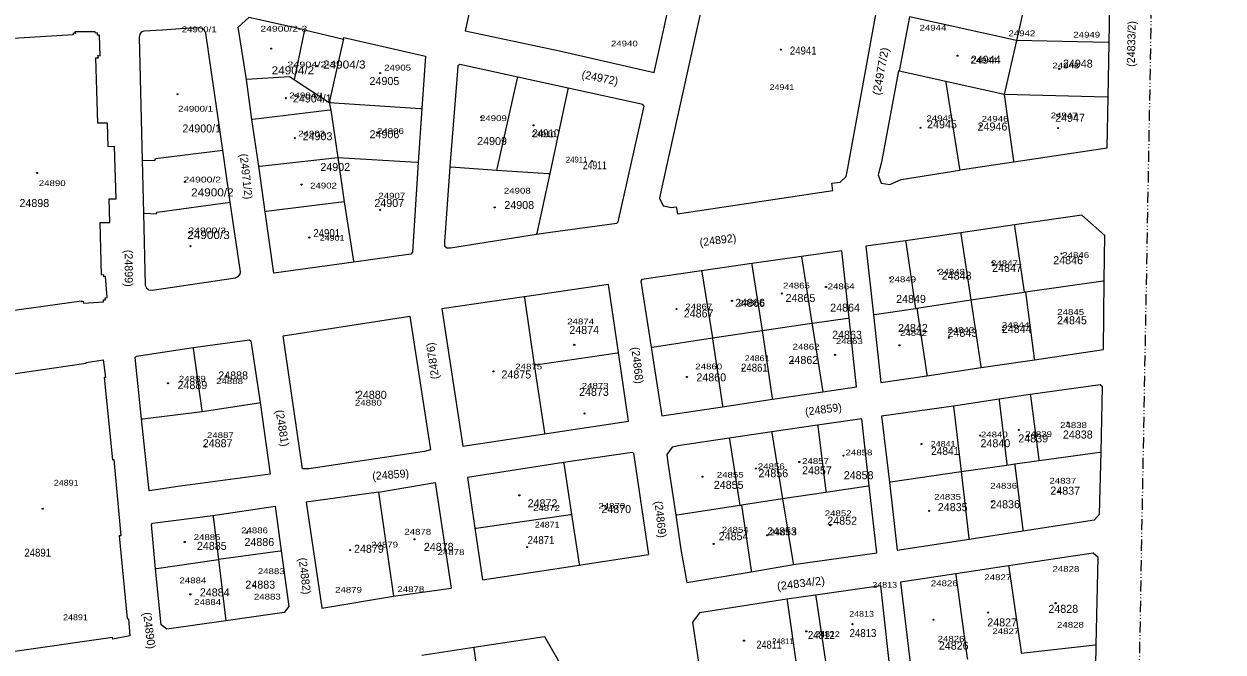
# Model space of a CAD drawing. Extents: x 649608 to 651081, y 237980 to 241202.
# Drawn here: x 650066 to 650605, y 240222 to 240505 of the extents above; entities that cross this region are included whole.
import ezdxf

# ---------------------------------------------------------------- set-up
doc = ezdxf.new("R2010")
doc.units = 0
doc.header["$PDMODE"] = 32
doc.header["$PDSIZE"] = 0.5
doc.linetypes.add('DASH_DOUBLE_DOT', pattern=[9.2, 5, -1.2, 0.3, -1.2, 0.3, -1.2])
for name, color, linetype in [('19', 7, 'Continuous'), ('20', 7, 'Continuous'), ('6', 7, 'Continuous')]:
    doc.layers.add(name, color=color, linetype=linetype)
for name, color, linetype, lineweight in [('3', 7, 'Continuous', 13), ('5', 7, 'Continuous', 13), ('52', 7, 'DASH_DOUBLE_DOT', 13)]:
    doc.layers.add(name, color=color, linetype=linetype, lineweight=lineweight)

msp = doc.modelspace()

# ---------------------------------------------------------------- linework, layer by layer
at = {"layer": '3'}
for p, q in [((650464.38, 240507.741), (650459.782, 240483.398)), ((650192.146, 240501.902), (650209.762, 240497.751)), ((650100.313, 240490.228), (650100.028, 240499.595)), ((650393.376, 240396.857), (650370.795, 240393.616)), ((650451.842, 240328.356), (650455.303, 240298.708)), ((650122.263, 240294.737), (650118.945, 240327.041)), ((650442.889, 240327.116), (650422.995, 240324.266)), ((650340.221, 240311.728), (650346.915, 240266.06)), ((650225.498, 240294.168), (650250.969, 240298.542)), ((650250.969, 240298.542), (650258.175, 240251.056)), ((650451.519, 240252.086), (650422.153, 240247.787)), ((650156.768, 240236.355), (650130.262, 240232.545))]:
    msp.add_line(p, q, dxfattribs=at)
for points in [[(650367.209, 240562.582), (650368.783, 240569.636), (650368.608, 240571.167), (650367.259, 240572.096), (650286.579, 240591.249), (650284.955, 240591.124), (650284.131, 240589.969), (650282.457, 240582.689), (650264.467, 240501.506)], [(650382.8, 240566.096), (650352.577, 240429.937), (650351.943, 240426.301), (650353.603, 240422.893), (650357.329, 240422.137), (650359.471, 240422.441), (650359.933, 240419.311), (650429.951, 240429.763), (650429.439, 240432.969), (650433.112, 240433.476), (650435.814, 240436.102), (650436.576, 240439.789), (650456.358, 240548.398)], [(650264.467, 240501.506), (650306.865, 240492.557), (650349.449, 240482.852), (650367.209, 240562.582)], [(650511.154, 240442.644), (650511.32, 240442.669), (650553.356, 240448.971), (650553.746, 240471.66), (650554.168, 240496.192), (650554.749, 240529.941)], [(650192.146, 240501.902), (650167.155, 240507.496), (650162.349, 240503.208)], [(650100.028, 240499.595), (650099.147, 240499.556), (650099.059, 240500.551), (650098.128, 240500.488), (650098.035, 240501.11), (650088.929, 240501.003), (650089.121, 240500.255), (650088.092, 240500.442), (650088.158, 240499.721), (650056.369, 240497.741)], [(650155.442, 240447.926), (650147.749, 240500.428), (650147.186, 240501.652), (650146.142, 240502.609), (650144.811, 240502.825), (650136.255, 240502.412), (650128.376, 240501.842), (650119.868, 240501.329), (650118.68, 240500.848), (650118.066, 240500.036), (650117.773, 240498.698), (650119.117, 240443.322), (650119.701, 240419.596)], [(650214.393, 240397.528), (650178.466, 240392.571), (650174.486, 240420.19), (650171.673, 240440.616), (650168.466, 240461.644), (650166.15, 240479.629), (650162.349, 240503.208)], [(650209.762, 240497.751), (650209.923, 240498.519), (650246.613, 240490.129), (650244.934, 240466.532), (650243.299, 240442.387)], [(650059.467, 240375.583), (650091.818, 240380.163), (650091.888, 240379.74), (650092.62, 240379.93), (650092.786, 240379.133), (650101.847, 240379.688), (650101.833, 240380.533), (650102.713, 240380.571), (650102.55, 240381.567), (650103.481, 240381.629), (650102.668, 240391.028), (650101.863, 240390.963), (650101.95, 240391.906), (650100.841, 240391.746), (650100.257, 240415.422), (650104.633, 240415.416), (650104.363, 240425.975), (650107.406, 240425.961), (650106.77, 240449.489), (650103.826, 240449.378), (650103.582, 240460.06), (650099.28, 240459.966), (650098.341, 240489.384), (650099.497, 240489.344), (650099.259, 240490.366), (650100.313, 240490.228)], [(650288.198, 240480.741), (650264.242, 240486.002), (650262.124, 240486.33), (650261.206, 240485.723), (650260.978, 240483.527), (650257.542, 240440.48), (650257.534, 240440.368)], [(650345.022, 240467.678), (650344.461, 240468.384), (650310.826, 240475.771), (650288.198, 240480.741)], [(650459.782, 240483.398), (650459.399, 240483.524), (650451.804, 240442.496), (650450.303, 240436.815), (650451.658, 240433.003), (650455.562, 240432.373), (650460.586, 240434.647), (650486.947, 240438.939)], [(650296.639, 240410.084), (650302.872, 240411.06), (650332.767, 240415.085), (650333.328, 240415.64), (650345.022, 240467.678)], [(650119.701, 240419.596), (650120.578, 240387.198), (650121.116, 240385.975), (650122.161, 240385.092), (650123.668, 240384.899), (650161.212, 240390.506), (650162.426, 240391.062), (650163.219, 240392.07), (650163.434, 240393.21), (650158.796, 240424.512), (650155.442, 240447.926)], [(650243.299, 240442.387), (650240.732, 240402.036), (650239.965, 240401.102), (650214.393, 240397.528)], [(650486.947, 240438.939), (650487.164, 240438.974), (650511.154, 240442.644)], [(650257.534, 240440.368), (650255.171, 240406.624), (650255.121, 240404.932), (650256.244, 240403.923), (650257.851, 240403.974), (650263.54, 240404.885), (650296.572, 240410.073), (650296.639, 240410.084)], [(650552.188, 240409.485), (650541.824, 240418.721), (650511.57, 240414.271), (650487.428, 240410.72), (650462.591, 240407.067)], [(650448.146, 240373.862), (650451.448, 240343.428), (650472.187, 240346.506), (650496.604, 240350.129), (650520.565, 240353.685), (650551.565, 240358.285), (650551.942, 240389.236), (650552.188, 240409.485)], [(650462.591, 240407.067), (650462.495, 240407.053), (650444.792, 240404.775), (650448.146, 240373.862)], [(650348.1, 240359.263), (650352.886, 240328.421), (650380.267, 240332.524), (650402.707, 240335.887), (650425.332, 240339.278), (650440.531, 240341.556), (650437.178, 240372.47), (650433.901, 240402.675)], [(650433.901, 240402.675), (650415.741, 240400.068), (650393.376, 240396.857)], [(650370.795, 240393.616), (650343.986, 240389.767), (650343.477, 240389.059), (650348.1, 240359.263)], [(650328.911, 240387.438), (650291.134, 240382.022), (650291.034, 240382.007)], [(650300.175, 240320.388), (650338.016, 240326.067), (650333.443, 240356.891), (650328.911, 240387.438)], [(650291.034, 240382.007), (650254.046, 240376.479), (650263.482, 240314.881), (650300.175, 240320.388)], [(650142.108, 240359.182), (650167.453, 240362.66), (650168.076, 240362.23), (650172.23, 240334.385)], [(650118.945, 240327.041), (650116.072, 240354.72), (650116.633, 240355.334), (650142.108, 240359.182)], [(650059.084, 240347.002), (650093.981, 240352.071), (650093.986, 240352.468), (650101.672, 240353.637), (650102.729, 240345.676), (650102.075, 240345.684), (650105.862, 240308.606), (650106.468, 240308.772), (650109.636, 240274.582), (650108.831, 240274.518), (650112.415, 240237.392), (650113.017, 240237.26), (650113.65, 240229.528), (650105.986, 240228.11), (650105.869, 240228.782), (650061.877, 240222.463)], [(650550.54, 240312.255), (650551.221, 240341.496), (650550.174, 240342.429), (650518.774, 240338), (650518.691, 240337.988), (650504.653, 240335.908), (650484.158, 240332.873), (650484.084, 240332.862), (650451.842, 240328.356)], [(650172.23, 240334.385), (650176.782, 240302.214), (650136.222, 240296.82), (650122.263, 240294.737)], [(650422.995, 240324.266), (650402.434, 240321.32), (650402.362, 240321.309), (650383.261, 240318.451)], [(650412.155, 240261.578), (650412.225, 240261.59), (650449.645, 240266.905), (650446.273, 240296.959), (650442.889, 240327.116)], [(650383.261, 240318.451), (650361.162, 240315.144), (650357.591, 240314.31), (650355.17, 240311.002), (650355.607, 240307.291), (650359.202, 240283.753)], [(650340.221, 240311.728), (650339.608, 240311.93), (650308.744, 240307.475), (650308.736, 240307.474)], [(650515.39, 240276.743), (650547.594, 240281.685), (650549.888, 240284.211), (650550.54, 240312.255)], [(650308.736, 240307.474), (650265.483, 240300.794), (650268.862, 240277.919)], [(650455.303, 240298.708), (650458.879, 240268.07), (650491.19, 240273.029), (650515.39, 240276.743)], [(650225.498, 240294.168), (650193.022, 240289.614), (650199.999, 240242.163), (650199.997, 240242.039), (650232.257, 240247.39), (650258.175, 240251.056)], [(650150.997, 240283.692), (650178.942, 240287.906), (650181.707, 240267.729)], [(650125.145, 240259.756), (650123.355, 240279.573), (650123.841, 240280.188), (650150.997, 240283.692)], [(650359.202, 240283.753), (650361.556, 240268.337), (650364.195, 240253.519), (650393.211, 240258.395), (650412.155, 240261.578)], [(650268.862, 240277.919), (650272.28, 240254.773), (650315.825, 240261.354)], [(650181.707, 240267.729), (650185.142, 240242.725), (650183.097, 240240.118), (650156.768, 240236.355)], [(650315.825, 240261.354), (650316.484, 240261.454), (650346.915, 240266.06)], [(650548.41, 240225.505), (650549.266, 240264.771), (650546.994, 240266.689), (650508.951, 240260.965), (650485.214, 240257.393), (650460.37, 240253.655)], [(650130.262, 240232.545), (650127.746, 240234.489), (650125.145, 240259.756)], [(650460.37, 240253.655), (650464.813, 240216.218), (650467.034, 240197.497), (650471.435, 240160.411)], [(650422.153, 240247.787), (650422.134, 240247.784), (650409.227, 240245.987), (650409.196, 240245.982)], [(650459.759, 240178.093), (650456.889, 240203.161), (650456.873, 240203.307), (650454.806, 240222.136), (650451.519, 240252.086)], [(650409.196, 240245.982), (650369.92, 240239.938), (650366.735, 240235.721), (650370.821, 240208.803), (650375.407, 240178.587), (650380.061, 240147.931), (650384.882, 240116.168), (650389.996, 240082.478)], [(650245.029, 240220.902), (650268.31, 240224.434), (650300.106, 240229.259)], [(650300.106, 240229.259), (650309.685, 240212.852), (650289.846, 240187.623), (650266.349, 240157.741), (650250.168, 240137.164)], [(650547.448, 240170.665), (650547.985, 240206.022), (650547.986, 240206.073), (650548.41, 240225.505)]]:
    msp.add_lwpolyline(points, dxfattribs=at)
msp.add_lwpolyline([(650182.541, 240364.455), (650239.541, 240373.241), (650248.9, 240313.168), (650246.225, 240312.432), (650194.192, 240304.7), (650191.374, 240304.636)], close=True, dxfattribs=at)
at = {"layer": '5'}
for p, q in [((650415.741, 240400.068), (650420.451, 240370.075)), ((650491.987, 240380.618), (650515.92, 240384.058)), ((650515.92, 240384.058), (650516.52, 240384.145)), ((650484.158, 240332.873), (650487.625, 240303.366)), ((650225.498, 240294.168), (650232.257, 240247.39)), ((650387.969, 240288.191), (650388.786, 240288.267))]:
    msp.add_line(p, q, dxfattribs=at)
for points in [[(650521.636, 240537.673), (650521.522, 240537.173), (650512.428, 240497.215), (650506.903, 240472.938)], [(650554.168, 240496.192), (650553.668, 240496.204), (650512.428, 240497.215), (650464.38, 240507.741)], [(650192.146, 240501.902), (650187.578, 240479.555), (650185.407, 240480.899), (650166.15, 240479.629)], [(650209.762, 240497.751), (650209.649, 240497.251), (650203.371, 240469.37), (650204.032, 240465.91), (650207.235, 240444.56), (650209.979, 240424.631)], [(650187.578, 240479.555), (650188.078, 240479.233), (650203.371, 240469.37)], [(650278.768, 240438.94), (650278.881, 240439.44), (650288.085, 240480.241), (650288.198, 240480.741)], [(650553.746, 240471.66), (650553.246, 240471.674), (650506.903, 240472.938), (650480.702, 240478.754), (650459.782, 240483.398)], [(650310.826, 240475.771), (650310.718, 240475.271), (650302.526, 240437.343)], [(650480.702, 240478.754), (650480.78, 240478.254), (650486.869, 240439.439), (650486.947, 240438.939)], [(650203.371, 240469.37), (650244.434, 240466.566), (650244.934, 240466.532)], [(650506.903, 240472.938), (650511.084, 240443.144), (650511.154, 240442.644)], [(650204.032, 240465.91), (650203.532, 240465.85), (650168.966, 240461.704), (650168.466, 240461.644)], [(650119.117, 240443.322), (650119.617, 240443.311), (650124.8, 240443.2), (650125.189, 240444.188), (650155.442, 240447.926)], [(650171.673, 240440.616), (650172.173, 240440.671), (650207.235, 240444.56)], [(650207.235, 240444.56), (650242.799, 240442.417), (650243.299, 240442.387)], [(650257.534, 240440.368), (650258.034, 240440.334), (650278.768, 240438.94)], [(650278.768, 240438.94), (650302.026, 240437.377), (650302.526, 240437.343)], [(650302.526, 240437.343), (650296.747, 240410.583), (650296.639, 240410.084)], [(650119.701, 240419.596), (650120.201, 240419.568), (650125.456, 240419.274), (650125.969, 240420.062), (650158.796, 240424.512)], [(650209.979, 240424.631), (650174.986, 240420.253), (650174.486, 240420.19)], [(650209.979, 240424.631), (650214.312, 240398.028), (650214.393, 240397.528)], [(650511.57, 240414.271), (650511.642, 240413.771), (650515.92, 240384.058)], [(650487.428, 240410.72), (650487.504, 240410.22), (650491.987, 240380.618)], [(650462.591, 240407.067), (650462.664, 240406.567), (650467.014, 240376.77)], [(650370.795, 240393.616), (650370.877, 240393.116), (650375.731, 240363.448)], [(650393.376, 240396.857), (650393.455, 240396.357), (650398.133, 240366.867)], [(650516.52, 240384.145), (650551.442, 240389.164), (650551.942, 240389.236)], [(650291.034, 240382.007), (650291.108, 240381.507), (650295.58, 240351.364)], [(650516.52, 240384.145), (650520.499, 240354.185), (650520.565, 240353.685)], [(650448.146, 240373.862), (650448.646, 240373.939), (650467.014, 240376.77), (650467.64, 240376.867)], [(650467.64, 240376.867), (650491.904, 240380.606), (650491.987, 240380.618)], [(650467.64, 240376.867), (650472.112, 240347.006), (650472.187, 240346.506)], [(650491.987, 240380.618), (650496.528, 240350.629), (650496.604, 240350.129)], [(650420.451, 240370.075), (650420.557, 240370.09), (650436.678, 240372.398), (650437.178, 240372.47)], [(650348.1, 240359.263), (650348.6, 240359.339), (650375.731, 240363.448), (650398.133, 240366.867), (650420.451, 240370.075)], [(650398.133, 240366.867), (650398.138, 240366.837), (650402.633, 240336.387), (650402.707, 240335.887)], [(650420.451, 240370.075), (650420.559, 240369.386), (650425.332, 240339.278)], [(650375.731, 240363.448), (650375.793, 240363.067), (650380.194, 240333.024), (650380.267, 240332.524)], [(650142.108, 240359.182), (650142.178, 240358.682), (650146.079, 240330.921), (650146.149, 240330.421)], [(650295.58, 240351.364), (650296.08, 240351.437), (650332.943, 240356.818), (650333.443, 240356.891)], [(650295.58, 240351.364), (650300.101, 240320.888), (650300.175, 240320.388)], [(650146.149, 240330.421), (650171.73, 240334.309), (650172.23, 240334.385)], [(650504.653, 240335.908), (650504.713, 240335.408), (650508.163, 240306.834), (650508.223, 240306.334)], [(650518.691, 240337.988), (650518.757, 240337.488), (650522.565, 240308.86), (650522.631, 240308.36)], [(650118.945, 240327.041), (650119.445, 240327.103), (650146.149, 240330.421)], [(650422.995, 240324.266), (650423.057, 240323.766), (650426.668, 240294.564), (650426.73, 240294.064)], [(650383.261, 240318.451), (650383.339, 240317.951), (650387.969, 240288.191)], [(650402.362, 240321.309), (650402.444, 240320.809), (650407.301, 240291.185)], [(650522.631, 240308.36), (650550.041, 240312.185), (650550.54, 240312.255)], [(650308.736, 240307.474), (650308.813, 240306.974), (650312.323, 240284.136)], [(650455.303, 240298.708), (650455.803, 240298.78), (650487.625, 240303.366), (650508.223, 240306.334), (650511.743, 240306.841)], [(650511.743, 240306.841), (650511.758, 240306.843), (650522.631, 240308.36)], [(650511.743, 240306.841), (650511.804, 240306.341), (650515.329, 240277.243), (650515.39, 240276.743)], [(650487.625, 240303.366), (650491.131, 240273.529), (650491.19, 240273.029)], [(650446.273, 240296.959), (650445.773, 240296.885), (650426.73, 240294.064), (650407.301, 240291.185), (650388.786, 240288.267)], [(650407.301, 240291.185), (650412.073, 240262.078), (650412.155, 240261.578)], [(650387.969, 240288.191), (650359.702, 240283.83), (650359.202, 240283.753)], [(650388.786, 240288.267), (650393.137, 240258.895), (650393.211, 240258.395)], [(650150.997, 240283.692), (650151.06, 240283.192), (650153.491, 240263.94), (650156.768, 240236.355)], [(650268.862, 240277.919), (650269.362, 240277.991), (650311.823, 240284.064), (650312.323, 240284.136)], [(650312.323, 240284.136), (650315.748, 240261.854), (650315.825, 240261.354)], [(650125.145, 240259.756), (650125.645, 240259.83), (650153.491, 240263.94)], [(650181.707, 240267.729), (650181.207, 240267.662), (650153.491, 240263.94)], [(650508.951, 240260.965), (650509.023, 240260.465), (650514.54, 240222.272), (650514.612, 240221.772)], [(650485.214, 240257.393), (650485.282, 240256.893), (650490.357, 240219.574), (650490.425, 240219.074)], [(650422.153, 240247.787), (650422.228, 240247.287), (650426.646, 240218.032), (650426.721, 240217.532)], [(650409.196, 240245.982), (650409.268, 240245.482), (650413.524, 240215.891), (650413.596, 240215.391)], [(650514.612, 240221.772), (650547.91, 240225.45), (650548.41, 240225.505)], [(650268.31, 240224.434), (650268.38, 240223.934), (650271.472, 240201.911)]]:
    msp.add_lwpolyline(points, dxfattribs=at)
at = {"layer": '52'}
msp.add_lwpolyline([(650605.404, 240765.589), (650575.102, 240622.376), (650564.111, 240019.547), (650563.292, 239912.239), (650561.967, 239831.306), (650558.948, 239635.138), (650557.76, 239590.469), (650555.824, 239499.761), (650555.114, 239481.758), (650553.994, 239393.396), (650554.019, 239393.395), (650553.222, 239318.763), (650553.006, 239301.006), (650586.911, 239277.281)], dxfattribs=at)
at = {"layer": '6'}
for p in [(650177.172, 240493.525), (650406.438, 240493.08), (650485.978, 240490.339), (650197.927, 240485.636), (650531.743, 240484.437), (650226.203, 240482.525), (650135.081, 240473.012), (650183.825, 240471.271), (650271.712, 240462.635), (650295.258, 240459.042), (650469.315, 240457.948), (650496.353, 240458.846), (650531.268, 240457.791), (650187.837, 240453.263), (650224.875, 240455.878), (650321.596, 240442.927), (650071.901, 240437.617), (650138.425, 240433.6), (650190.86, 240432.375), (650226.252, 240421.044), (650277.751, 240422.145), (650194.373, 240408.601), (650140.917, 240404.705), (650532.757, 240401.389), (650477.267, 240393.745), (650501.716, 240397.444), (650455.68, 240390.464), (650406.924, 240383.467), (650426.78, 240386.375), (650359.52, 240376.439), (650384.512, 240380.152), (650534.965, 240371.46), (650506.404, 240367.137), (650313.584, 240360.382), (650459.889, 240360.147), (650482.101, 240363.562), (650430.84, 240355.874), (650389.21, 240349.695), (650411.672, 240352.981), (650157.15, 240346.54), (650277.177, 240348.444), (650364.236, 240345.934), (650130.822, 240343.111), (650215.597, 240338.938), (650318.163, 240329.513), (650535.606, 240325.394), (650496.165, 240319.637), (650513.554, 240322.161), (650147.631, 240314.561), (650469.737, 240315.79), (650414.815, 240307.725), (650434.715, 240310.59), (650371.256, 240301.102), (650395.235, 240304.75), (650288.843, 240292.696), (650501.497, 240289.935), (650531.683, 240294.499), (650074.416, 240286.684), (650327.918, 240286.642), (650473.259, 240285.718), (650428.756, 240279.268), (650166.281, 240275.923), (650400.386, 240274.79), (650138.286, 240271.724), (650241.706, 240272.966), (650292.346, 240269.454), (650376.263, 240270.893), (650212.725, 240268.103), (650140.843, 240248.242), (650169.383, 240252.042), (650530.093, 240244.23), (650475.192, 240236.805), (650499.777, 240240.019), (650417.932, 240231.589), (650438.764, 240234.809), (650389.935, 240227.392)]:
    msp.add_point(p, dxfattribs=at)

# ---------------------------------------------------------------- texts
at = {"layer": '19'}
for s, rotation, p in [('(24833/2)', 88.873, (650565.736, 240485.298)), ('(24972)', 348.809, (650316.652, 240480.28)), ('(24971/2)', 276.354, (650163.054, 240446.117)), ('(24892)', 7.507, (650370.185, 240404.605)), ('(24899)', 270, (650111.35, 240403.086)), ('(24876)', 98.015, (650252.764, 240345.162)), ('(24868)', 276.795, (650339.202, 240359.177)), ('(24859)', 7.59, (650417.629, 240328.493)), ('(24881)', 279.003, (650179.199, 240330.855)), ('(24859)', 4.622, (650222.821, 240299.576)), ('(24869)', 276.723, (650349.62, 240289.946)), ('(24882)', 277.149, (650189.529, 240264.482)), ('(24890)', 277.148, (650119.596, 240239.964))]:
    msp.add_text(s, height=3.6, rotation=rotation, dxfattribs=at).set_placement(p)
for s, width, p in [('24941', 0.9, (650410.541, 240490.861)), ('24904/2', 1.1, (650177.4, 240481.949)), ('24904/3', 1.1, (650200.522, 240484.561)), ('24910', 0.9, (650294.754, 240453.651)), ('24911', 0.8, (650317.44, 240439.285)), ('24900/2', 1.1, (650141.191, 240427.096)), ('24900/3', 1.1, (650139.446, 240407.942)), ('24901', 0.9, (650196.159, 240408.812)), ('24861', 0.9, (650388.55, 240348.299)), ('24841', 0.95, (650474.057, 240310.86)), ('24871', 0.9, (650292.574, 240270.81)), ('24891', 0.9, (650066.154, 240265.149)), ('24812', 0.9, (650418.652, 240228.146)), ('24813', 0.9, (650437.411, 240229.017)), ('24811', 0.85, (650395.53, 240223.793))]:
    msp.add_text(s, height=3.6, dxfattribs=dict(at, width=width)).set_placement(p)
at = {"layer": '19', "width": 1.05}
for s, rotation, p in [('(24977/2)', 79.659, (650451.208, 240472.367)), ('(24834/2)', 7.213, (650405.004, 240250.05))]:
    msp.add_text(s, height=3.6, rotation=rotation, dxfattribs=at).set_placement(p)
at = {"layer": '19'}
for s, p in [('24944', (650491.945, 240486.737)), ('24948', (650533.39, 240484.995)), ('24905', (650221.462, 240477.16)), ('24904/1', (650186.998, 240469.324)), ('24947', (650529.901, 240460.616)), ('24900/1', (650137.264, 240455.829)), ('24945', (650472.284, 240457.71)), ('24946', (650495, 240456.698)), ('24903', (650191.36, 240452.346)), ('24906', (650221.463, 240453.216)), ('24909', (650269.888, 240450.169)), ('24902', (650199.334, 240438.504)), ('24898', (650063.974, 240422.307)), ('24907', (650223.645, 240422.307)), ('24908', (650282.102, 240421.436)), ('24846', (650529.026, 240396.622)), ('24848', (650478.856, 240389.657)), ('24847', (650501.541, 240393.139)), ('24865', (650408.618, 240379.644)), ('24849', (650458.352, 240379.209)), ('24866', (650385.933, 240377.467)), ('24864', (650428.685, 240375.29)), ('24867', (650362.811, 240372.678)), ('24845', (650530.771, 240369.631)), ('24874', (650311.332, 240365.277)), ('24863', (650429.558, 240363.101)), ('24842', (650459.224, 240366.148)), ('24843', (650481.473, 240363.972)), ('24844', (650505.904, 240365.713)), ('24862', (650409.926, 240351.782)), ('24889', (650135.084, 240340.464)), ('24888', (650153.406, 240344.817)), ('24875', (650280.794, 240345.252)), ('24860', (650368.481, 240343.946)), ('24880', (650215.792, 240336.11)), ('24873', (650315.695, 240337.416)), ('24887', (650146.427, 240314.343)), ('24840', (650496.306, 240314.343)), ('24839', (650513.32, 240316.52)), ('24838', (650533.387, 240318.261)), ('24856', (650396.404, 240300.848)), ('24857', (650416.036, 240302.154)), ('24858', (650434.794, 240299.977)), ('24855', (650376.335, 240295.624)), ('24837', (650527.717, 240293.011)), ('24872', (650292.574, 240287.353)), ('24836', (650500.669, 240286.917)), ('24870', (650325.728, 240284.74)), ('24835', (650477.11, 240285.61)), ('24852', (650427.377, 240279.516)), ('24854', (650378.516, 240272.551)), ('24853', (650400.329, 240274.727)), ('24885', (650143.809, 240268.196)), ('24886', (650165.187, 240269.938)), ('24879', (650214.484, 240266.891)), ('24878', (650245.893, 240267.762)), ('24883', (650165.622, 240250.783)), ('24884', (650145.118, 240247.3)), ('24828', (650526.845, 240239.9)), ('24827', (650499.362, 240233.805)), ('24826', (650477.549, 240223.357))]:
    msp.add_text(s, height=3.6, dxfattribs=at).set_placement(p)
at = {"layer": '20'}
for s, width, p in [('24900/1', 1.25, (650136.971, 240500.87)), ('24900/2-3', 1.35, (650172.325, 240501.148)), ('24944', 1.25, (650468.88, 240501.601)), ('24942', 1.25, (650508.878, 240499.101)), ('24949', 1.25, (650538.043, 240498.465)), ('24940', 1.25, (650330.049, 240494.506)), ('24904/2-3', 1.4, (650184.468, 240485.086)), ('24905', 1.25, (650228.035, 240483.674)), ('24944', 1.25, (650491.754, 240486.962)), ('24948', 1.25, (650528.659, 240484.612)), ('24904/1', 1.25, (650185.319, 240471.184)), ('24941', 1.15, (650401.394, 240474.873)), ('24900/1', 1.25, (650135.357, 240465.185)), ('24909', 1.25, (650271.129, 240460.938)), ('24945', 1.25, (650471.98, 240460.903)), ('24946', 1.25, (650496.809, 240460.659)), ('24947', 1.25, (650527.895, 240462.183)), ('24906', 1.25, (650224.819, 240455.163)), ('24903', 1.25, (650189.396, 240454.022)), ('24910', 1.15, (650294.254, 240453.739)), ('24900/2', 1.35, (650137.736, 240433.348)), ('24890', 1.25, (650072.667, 240431.747)), ('24902', 1.25, (650194.695, 240430.634)), ('24908', 1.25, (650281.879, 240428.334)), ('24907', 1.25, (650225.421, 240426.108)), ('24900/3', 1.35, (650139.963, 240410.488)), ('24901', 1.15, (650199.081, 240407.172)), ('24847', 1.25, (650501.06, 240395.751)), ('24846', 1.25, (650533.086, 240399.433)), ('24848', 1.25, (650477.264, 240391.936)), ('24865', 1.25, (650407.476, 240385.707)), ('24864', 1.25, (650427.557, 240385.342)), ('24849', 1.25, (650455.238, 240388.521)), ('24867', 1.25, (650363.557, 240376.284)), ('24866', 1.25, (650387.29, 240377.961)), ('24845', 1.25, (650530.849, 240373.825)), ('24874', 1.25, (650310.395, 240369.585)), ('24842', 1.25, (650460.111, 240364.415)), ('24843', 1.25, (650481.426, 240365.749)), ('24844', 1.3, (650505.811, 240367.946)), ('24862', 1.25, (650411.784, 240358.248)), ('24863', 1.25, (650431.258, 240360.716)), ('24861', 1.15, (650390.253, 240353.046)), ('24875', 1.25, (650287.027, 240349.318)), ('24860', 1.25, (650368.015, 240349.346)), ('24889', 1.25, (650135.691, 240343.825)), ('24888', 1.25, (650152.455, 240342.743)), ('24873', 1.25, (650316.917, 240340.647)), ('24880', 1.25, (650214.891, 240333.067)), ('24838', 1.25, (650532.096, 240322.99)), ('24887', 1.25, (650148.309, 240318.487)), ('24841', 1.15, (650473.932, 240314.553)), ('24840', 1.25, (650496.481, 240318.77)), ('24839', 1.25, (650516.376, 240318.943)), ('24858', 1.25, (650435.585, 240310.696)), ('24856', 1.25, (650396.142, 240304.46)), ('24857', 1.25, (650416.04, 240306.83)), ('24855', 1.25, (650377.668, 240300.645)), ('24891', 1.15, (650079.438, 240297.087)), ('24836', 1.25, (650500.686, 240295.717)), ('24837', 1.25, (650527.286, 240297.972)), ('24835', 1.25, (650475.448, 240290.736)), ('24872', 1.25, (650295.016, 240285.741)), ('24870', 1.25, (650324.407, 240286.666)), ('24852', 1.25, (650426.242, 240283.361)), ('24871', 1.15, (650295.791, 240278.226)), ('24885', 1.25, (650142.348, 240272.608)), ('24886', 1.25, (650163.674, 240275.692)), ('24878', 1.25, (650237.113, 240275.058)), ('24854', 1.25, (650379.934, 240275.961)), ('24853', 1.25, (650401.375, 240274.805)), ('24879', 1.25, (650222.2, 240269.282)), ('24878', 1.25, (650252.05, 240265.864)), ('24883', 1.25, (650171.213, 240257.312)), ('24828', 1.25, (650528.68, 240258.348)), ('24884', 1.25, (650135.938, 240253.199)), ('24813', 1.15, (650447.656, 240251.19)), ('24826', 1.25, (650473.965, 240251.884)), ('24827', 1.25, (650498.04, 240254.591)), ('24883', 1.25, (650169.431, 240245.863)), ('24879', 1.25, (650205.975, 240248.945)), ('24878', 1.25, (650233.981, 240249.246)), ('24884', 1.25, (650142.61, 240243.453)), ('24891', 1.15, (650083.601, 240236.6)), ('24813', 1.15, (650437.242, 240238.135)), ('24812', 1.15, (650421.903, 240229.066)), ('24827', 1.25, (650501.628, 240230.368)), ('24828', 1.25, (650530.725, 240233.237)), ('24826', 1.25, (650477.001, 240226.944))]:
    msp.add_text(s, height=2.6, dxfattribs=dict(at, width=width)).set_placement(p)
for s, p in [('24911', (650309.8, 240442.324)), ('24811', (650402.579, 240225.826))]:
    msp.add_text(s, height=2.6, dxfattribs=at).set_placement(p)

doc.saveas('drawing.dxf')
